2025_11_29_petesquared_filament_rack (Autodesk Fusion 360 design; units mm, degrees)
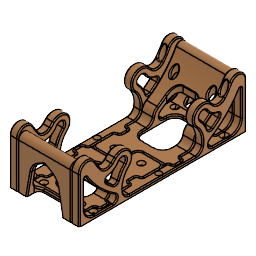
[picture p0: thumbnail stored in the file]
parameter "global_cutout_corner_round" = 25.4
parameter "hole_screw" = 3.2004
parameter "hole_screwhead" = 7.112
parameter "d545" = 25.4
parameter "d546" = 25.4 (= "d545")
sketch "filament_rack_side" plane through (0, 0, 0) normal (1, 0, 0) x axis (0, 1, 0)
  line L1 (-10.5228, -408.051) -> (33.0228, -408.051)
  line L2 (134.6228, -401.701) -> (134.6228, -300.101)
  line L3 (238.7628, -300.101) -> (238.7628, -408.051)
  line L4 (134.6228, -408.051) -> (134.6228, -404.241)
  line L5 (238.7628, -408.051) -> (134.6228, -408.051)
  line L6 (236.2228, -300.101) -> (134.6228, -300.101)
  line L7 (232.4128, -391.541) -> (232.4128, -358.92)
  line L8 (219.7128, -404.241) -> (196.5801, -404.241)
  line L9 (175.7042, -404.241) -> (134.6228, -404.241)
  line L10 (121.9228, -404.241) -> (134.6228, -404.241)
  line L11 (121.9228, -408.051) -> (121.9228, -404.241)
  line L12 (134.6228, -408.051) -> (121.9228, -408.051)
  line L13 (198.0923, -359.4264) -> (194.1136, -355.4477)
  circle C1 centre (134.6228, -300.101) radius 101.6
  circle C2 centre (134.6228, -300.101) radius 104.14
  arc A1 centre (232.4128, -351.5321) radius 6.35 clockwise from (226.7927, -348.5763) to (238.7628, -351.5321)
  arc A2 centre (134.6228, -300.101) radius 111.76 clockwise from (230.0583, -358.2591) to (193.8863, -394.854)
  arc A3 centre (219.7128, -391.541) radius 12.7 clockwise from (232.4128, -391.541) to (219.7128, -404.241)
  arc A4 centre (196.5801, -399.161) radius 5.08 clockwise from (196.5801, -404.241) to (193.8863, -394.854)
  arc A5 centre (231.1428, -358.92) radius 1.27 clockwise from (230.0583, -358.2591) to (232.4128, -358.92)
  arc A6 centre (175.7042, -395.7956) radius 8.4454 clockwise from (184.0419, -397.1397) to (175.7042, -404.241)
  arc A7 centre (196.5801, -399.161) radius 12.7 clockwise from (184.0419, -397.1397) to (189.8456, -388.3936)
  arc A8 centre (134.6228, -300.101) radius 96.52 clockwise from (219.2429, -346.5289) to (197.3331, -373.4736)
  arc A9 centre (228.3617, -351.5321) radius 10.4011 clockwise from (219.2429, -346.5289) to (238.7628, -351.5321)
  arc A10 centre (222.9164, -403.4067) radius 39.3763 clockwise from (184.0419, -397.1397) to (197.3331, -373.4736)
  arc A11 centre (157.3505, -392.8368) radius 27.036 clockwise from (176.2537, -373.5077) to (184.0419, -397.1397)
  arc A12 centre (185.1334, -364.428) radius 12.7 clockwise from (176.2537, -373.5077) to (194.1136, -355.4477)
  arc A13 centre (204.3785, -353.1402) radius 8.89 clockwise from (211.4552, -358.521) to (198.0923, -359.4264)
  arc A14 centre (157.3505, -392.8368) radius 34.656 clockwise from (181.5815, -368.0599) to (191.5609, -387.2973)
  arc A15 centre (204.3785, -353.8284) radius 16.891 clockwise from (213.6024, -367.9785) to (189.5831, -361.9772)
  arc A16 centre (185.1334, -364.428) radius 5.08 clockwise from (181.5815, -368.0599) to (189.5831, -361.9772)
  point P2 (134.6228, -300.101)
  point P5 (134.6228, -300.101)
  point P6 (134.6228, -401.701)
  point P10 (238.7628, -300.101)
  point P3 (33.0228, -408.051)
  point P11 (238.7628, -408.051)
  point P8 (134.6228, -404.241)
  point P14 (226.7927, -348.5763)
  point P13 (238.7628, -351.5321)
  point P16 (134.6228, -300.101)
  point P17 (236.2228, -300.101)
  point P9 (238.7628, -408.051)
  point P31 (189.8456, -388.3936)
  point P26 (196.5801, -399.161)
  point P32 (196.5801, -399.161)
  point P30 (175.7042, -395.7956)
  point P23 (196.5801, -404.241)
  point P28 (175.7042, -404.241)
  point P35 (134.6228, -300.101)
  point P45 (211.4552, -358.521)
  point P40 (176.2537, -373.5077)
  point P42 (176.2537, -373.5077)
  point P50 (191.5609, -387.2973)
  point P53 (189.5831, -361.9772)
  point P54 (213.6024, -367.9785)
  point P55 (189.5831, -361.9772)
  point P47 (204.3785, -353.1402)
  point P52 (204.3785, -353.8284)
  point P33 (121.9228, -404.241)
  point P44 (185.1334, -364.428)
  coincident P2 P5
  vertical L2
  coincident C1 P6
  coincident C2 P10
  vertical L3
  horizontal P3 P11
  vertical P6 P8
  horizontal L5
  tangent C2 A1
  coincident C2 P14
  coincident L3 P13
  tangent L3 A1
  coincident P2 P16
  coincident C1 P17
  perpendicular L2 L6
  horizontal P10 P17
  vertical L7
  horizontal L8
  tangent L8 A3
  tangent L7 A3
  tangent L8 A4
  tangent L7 A5
  tangent A2 A5
  coincident P9 P11
  vertical L4
  coincident C2 P8
  tangent C2 L9
  tangent L9 A6
  tangent C2 A7
  coincident C2 P31
  tangent A6 A7
  coincident P26 P32
  tangent C2 L10
  perpendicular L5 L11
  perpendicular L4 L12
  coincident C2 P30
  horizontal P23 P28
  coincident P5 P35
  tangent L3 A9
  tangent A8 A9
  tangent A8 A10
  tangent A6 A10
  tangent A10 A11
  coincident A8 P45
  tangent A8 A13
  tangent A12 L13
  tangent A13 L13
  coincident P40 P42
  tangent A11 A12
  concentric A12 A16
  tangent A14 A16
  concentric A11 A14
  coincident C2 P50
  coincident P53 A16
  coincident C2 P54
  coincident A15 P55
  tangent A2 A4
  tangent A15 A16
  vertical P47 P52
  dimension "d2084" diameter C1 = 203.2
  dimension "d2088" distance P3 L2 = 101.6
  dimension "d2089" distance P3 P6 = 6.35
  dimension "d2090" = 2.54
  dimension "d2092" radius A1 = 6.35 (= "global_cutout_corner_round / 4")
  dimension "d2093" radius A3 = 12.7
  dimension "d2094" distance L3 L7 = 6.35
  dimension "d2096" radius A4 = 5.08
  dimension "d2097" radius A5 = 1.27
  dimension "d2100" distance C1 A2 = 10.16
  dimension "d2101" distance P8 P33 = 12.7
  dimension "d2200" distance C1 A8 = 5.08
  dimension "d2205" radius A12 = 12.7
  dimension "d2207" radius A13 = 8.89
  dimension "d2208" angle L5 L13 = 45
  dimension "d2209" distance P9 P45 = 49.53
  dimension "d2210" diameter A16 = 10.16
  dimension "d2212" distance C2 P44 = 22.352
  dimension "d2213" radius A15 = 16.891
extrude "Extrude1" new body sketch "filament_rack_side" profile of C2 L3 L4 L5 A1 A2 L7 L8 A3 A4 A5 L9 A6 A7 L10 L11 L12 along normal blind 66.675 (= "2 5/8")
sketch "filament_rack_bottom" plane through (0, 0, -408.051) normal (0, 0, 1) x axis (1, 0, 0)
  line L1 (0, 134.6228) -> (0, 121.9228)
  line L2 (0, 238.7628) -> (0, 134.6228)
  line L3 (0, 134.6228) -> (66.675, 134.6228)
  line L4 (66.675, 238.7628) -> (0, 238.7628)
  line L5 (66.675, 134.6228) -> (66.675, 238.7628)
  line L6 (40.9575, 210.8228) -> (25.7175, 210.8228)
  line L7 (51.1175, 170.1828) -> (51.1175, 200.6628)
  line L8 (25.7175, 160.0228) -> (40.9575, 160.0228)
  line L9 (15.5575, 200.6628) -> (15.5575, 170.1828)
  line L10 (66.675, 134.6228) -> (66.675, 121.9228)
  line L11 (66.675, 219.7128) -> (0, 219.7128)
  line L12 (66.675, 147.3228) -> (0, 147.3228)
  line L13 (73.025, 200.0278) -> (73.025, 206.3778)
  line L14 (60.325, 200.0278) -> (60.325, 206.3778)
  line L15 (66.675, 121.9228) -> (0, 121.9228)
  line L16 (33.3375, 238.7628) -> (33.3375, 121.9228)
  line L17 (72.8726, 200.0278) -> (72.8726, 206.3778)
  line L18 (60.4774, 200.0278) -> (60.4774, 206.3778)
  line L19 (-6.1976, 200.0278) -> (-6.1976, 206.3778)
  line L20 (6.1976, 200.0278) -> (6.1976, 206.3778)
  line L21 (6.35, 200.0278) -> (6.35, 206.3778)
  line L22 (-6.35, 200.0278) -> (-6.35, 206.3778)
  line L23 (66.675, 180.3428) -> (0, 180.3428)
  line L24 (0, 238.7628) -> (0, 30.4828)
  line L25 (60.325, 160.6578) -> (60.325, 154.3078)
  line L26 (72.8726, 160.6578) -> (72.8726, 154.3078)
  line L27 (60.4774, 160.6578) -> (60.4774, 154.3078)
  line L28 (73.025, 160.6578) -> (73.025, 154.3078)
  line L29 (-6.1976, 160.6578) -> (-6.1976, 154.3078)
  line L30 (6.1976, 160.6578) -> (6.1976, 154.3078)
  line L31 (6.35, 160.6578) -> (6.35, 154.3078)
  line L32 (-6.35, 160.6578) -> (-6.35, 154.3078)
  line L33 (26.9875, 128.2728) -> (6.35, 128.2728)
  arc A1 centre (6.35, 128.2728) radius 6.35 clockwise from (6.35, 121.9228) to (0, 128.2728)
  arc A2 centre (26.9875, 128.2728) radius 6.35 clockwise from (33.3375, 128.2728) to (26.9875, 121.9228)
  circle C1 centre (16.6688, 134.6228) radius 1.6002
  arc A3 centre (25.7175, 200.6628) radius 10.16 clockwise from (15.5575, 200.6628) to (25.7175, 210.8228)
  arc A4 centre (40.9575, 200.6628) radius 10.16 clockwise from (40.9575, 210.8228) to (51.1175, 200.6628)
  arc A5 centre (40.9575, 170.1828) radius 10.16 clockwise from (51.1175, 170.1828) to (40.9575, 160.0228)
  arc A6 centre (25.7175, 170.1828) radius 10.16 clockwise from (25.7175, 160.0228) to (15.5575, 170.1828)
  circle C2 centre (10.16, 216.1568) radius 1.6002
  circle C3 centre (10.16, 216.1568) radius 3.556
  circle C4 centre (56.515, 216.1568) radius 1.6002
  circle C5 centre (56.515, 216.1568) radius 3.556
  arc A7 centre (39.6875, 140.9728) radius 6.35 clockwise from (33.3375, 140.9728) to (39.6875, 147.3228)
  arc A8 centre (69.85, 212.7278) radius 3.175 clockwise from (69.85, 209.5528) to (66.675, 212.7278)
  arc A9 centre (69.85, 206.3778) radius 3.175 clockwise from (69.85, 209.5528) to (73.025, 206.3778)
  arc A10 centre (69.85, 200.0278) radius 3.175 clockwise from (73.025, 200.0278) to (69.85, 196.8528)
  arc A11 centre (69.85, 193.6778) radius 3.175 clockwise from (66.675, 193.6778) to (69.85, 196.8528)
  arc A12 centre (63.5, 193.6778) radius 3.175 clockwise from (63.5, 196.8528) to (66.675, 193.6778)
  arc A13 centre (63.5, 200.0278) radius 3.175 clockwise from (63.5, 196.8528) to (60.325, 200.0278)
  arc A14 centre (63.5, 212.7278) radius 3.175 clockwise from (66.675, 212.7278) to (63.5, 209.5528)
  arc A15 centre (63.5, 206.3778) radius 3.175 clockwise from (60.325, 206.3778) to (63.5, 209.5528)
  arc A16 centre (69.85, 212.7278) radius 3.3274 clockwise from (69.85, 209.4004) to (66.675, 211.7323)
  arc A17 centre (69.85, 206.3778) radius 3.0226 clockwise from (69.85, 209.4004) to (72.8726, 206.3778)
  arc A18 centre (69.85, 200.0278) radius 3.0226 clockwise from (72.8726, 200.0278) to (69.85, 197.0052)
  arc A19 centre (69.85, 193.6778) radius 3.3274 clockwise from (66.675, 194.6733) to (69.85, 197.0052)
  arc A20 centre (63.5, 193.6778) radius 3.3274 clockwise from (63.5, 197.0052) to (66.675, 194.6733)
  arc A21 centre (63.5, 200.0278) radius 3.0226 clockwise from (63.5, 197.0052) to (60.4774, 200.0278)
  arc A22 centre (63.5, 206.3778) radius 3.0226 clockwise from (60.4774, 206.3778) to (63.5, 209.4004)
  arc A23 centre (63.5, 212.7278) radius 3.3274 clockwise from (66.675, 211.7323) to (63.5, 209.4004)
  arc A24 centre (-3.175, 206.3778) radius 3.0226 clockwise from (-6.1976, 206.3778) to (-3.175, 209.4004)
  arc A25 centre (-3.175, 200.0278) radius 3.0226 clockwise from (-3.175, 197.0052) to (-6.1976, 200.0278)
  arc A26 centre (-3.175, 193.6778) radius 3.3274 clockwise from (-3.175, 197.0052) to (0, 194.6733)
  arc A27 centre (3.175, 193.6778) radius 3.3274 clockwise from (0, 194.6733) to (3.175, 197.0052)
  arc A28 centre (3.175, 200.0278) radius 3.0226 clockwise from (6.1976, 200.0278) to (3.175, 197.0052)
  arc A29 centre (3.175, 206.3778) radius 3.0226 clockwise from (3.175, 209.4004) to (6.1976, 206.3778)
  arc A30 centre (-3.175, 212.7278) radius 3.3274 clockwise from (0, 211.7323) to (-3.175, 209.4004)
  arc A31 centre (3.175, 212.7278) radius 3.3274 clockwise from (3.175, 209.4004) to (0, 211.7323)
  arc A32 centre (3.175, 193.6778) radius 3.175 clockwise from (0, 193.6778) to (3.175, 196.8528)
  arc A33 centre (3.175, 200.0278) radius 3.175 clockwise from (6.35, 200.0278) to (3.175, 196.8528)
  arc A34 centre (3.175, 206.3778) radius 3.175 clockwise from (3.175, 209.5528) to (6.35, 206.3778)
  arc A35 centre (3.175, 212.7278) radius 3.175 clockwise from (3.175, 209.5528) to (0, 212.7278)
  arc A36 centre (-3.175, 206.3778) radius 3.175 clockwise from (-6.35, 206.3778) to (-3.175, 209.5528)
  arc A37 centre (-3.175, 200.0278) radius 3.175 clockwise from (-3.175, 196.8528) to (-6.35, 200.0278)
  arc A38 centre (-3.175, 193.6778) radius 3.175 clockwise from (-3.175, 196.8528) to (0, 193.6778)
  arc A39 centre (-3.175, 212.7278) radius 3.175 clockwise from (0, 212.7278) to (-3.175, 209.5528)
  arc A40 centre (63.5, 147.9578) radius 3.175 clockwise from (63.5, 151.1328) to (66.675, 147.9578)
  arc A41 centre (63.5, 154.3078) radius 3.175 clockwise from (63.5, 151.1328) to (60.325, 154.3078)
  arc A42 centre (63.5, 160.6578) radius 3.175 clockwise from (60.325, 160.6578) to (63.5, 163.8328)
  arc A43 centre (63.5, 167.0078) radius 3.175 clockwise from (66.675, 167.0078) to (63.5, 163.8328)
  arc A44 centre (63.5, 167.0078) radius 3.3274 clockwise from (66.675, 166.0123) to (63.5, 163.6804)
  arc A45 centre (69.85, 167.0078) radius 3.3274 clockwise from (69.85, 163.6804) to (66.675, 166.0123)
  arc A46 centre (69.85, 160.6578) radius 3.0226 clockwise from (69.85, 163.6804) to (72.8726, 160.6578)
  arc A47 centre (69.85, 154.3078) radius 3.0226 clockwise from (72.8726, 154.3078) to (69.85, 151.2852)
  arc A48 centre (69.85, 147.9578) radius 3.3274 clockwise from (66.675, 148.9533) to (69.85, 151.2852)
  arc A49 centre (63.5, 147.9578) radius 3.3274 clockwise from (63.5, 151.2852) to (66.675, 148.9533)
  arc A50 centre (63.5, 154.3078) radius 3.0226 clockwise from (63.5, 151.2852) to (60.4774, 154.3078)
  arc A51 centre (63.5, 160.6578) radius 3.0226 clockwise from (60.4774, 160.6578) to (63.5, 163.6804)
  arc A52 centre (69.85, 147.9578) radius 3.175 clockwise from (66.675, 147.9578) to (69.85, 151.1328)
  arc A53 centre (69.85, 154.3078) radius 3.175 clockwise from (73.025, 154.3078) to (69.85, 151.1328)
  arc A54 centre (69.85, 160.6578) radius 3.175 clockwise from (69.85, 163.8328) to (73.025, 160.6578)
  arc A55 centre (69.85, 167.0078) radius 3.175 clockwise from (69.85, 163.8328) to (66.675, 167.0078)
  arc A56 centre (3.175, 160.6578) radius 3.0226 clockwise from (3.175, 163.6804) to (6.1976, 160.6578)
  arc A57 centre (3.175, 167.0078) radius 3.3274 clockwise from (3.175, 163.6804) to (0, 166.0123)
  arc A58 centre (-3.175, 167.0078) radius 3.3274 clockwise from (0, 166.0123) to (-3.175, 163.6804)
  arc A59 centre (-3.175, 160.6578) radius 3.0226 clockwise from (-6.1976, 160.6578) to (-3.175, 163.6804)
  arc A60 centre (-3.175, 154.3078) radius 3.0226 clockwise from (-3.175, 151.2852) to (-6.1976, 154.3078)
  arc A61 centre (-3.175, 147.9578) radius 3.3274 clockwise from (-3.175, 151.2852) to (0, 148.9533)
  arc A62 centre (3.175, 147.9578) radius 3.3274 clockwise from (0, 148.9533) to (3.175, 151.2852)
  arc A63 centre (3.175, 154.3078) radius 3.0226 clockwise from (6.1976, 154.3078) to (3.175, 151.2852)
  arc A64 centre (3.175, 147.9578) radius 3.175 clockwise from (0, 147.9578) to (3.175, 151.1328)
  arc A65 centre (3.175, 154.3078) radius 3.175 clockwise from (6.35, 154.3078) to (3.175, 151.1328)
  arc A66 centre (3.175, 160.6578) radius 3.175 clockwise from (3.175, 163.8328) to (6.35, 160.6578)
  arc A67 centre (3.175, 167.0078) radius 3.175 clockwise from (3.175, 163.8328) to (0, 167.0078)
  arc A68 centre (-3.175, 147.9578) radius 3.175 clockwise from (-3.175, 151.1328) to (0, 147.9578)
  arc A69 centre (-3.175, 154.3078) radius 3.175 clockwise from (-3.175, 151.1328) to (-6.35, 154.3078)
  arc A70 centre (-3.175, 160.6578) radius 3.175 clockwise from (-6.35, 160.6578) to (-3.175, 163.8328)
  arc A71 centre (-3.175, 167.0078) radius 3.175 clockwise from (0, 167.0078) to (-3.175, 163.8328)
  circle C6 centre (-5.08, 134.6228) radius 1.6002
  circle C7 centre (-5.08, 216.1568) radius 1.6002
  circle C8 centre (-5.08, 216.1568) radius 3.556
  point P3 (0, 134.6228)
  point P6 (0, 134.6228)
  point P4 (0, 238.7628)
  point P7 (0, 238.7628)
  point P9 (0, 128.2728)
  point P28 (33.3375, 160.0228)
  point P36 (0, 147.3228)
  point P37 (66.675, 147.3228)
  point P39 (39.6875, 147.3228)
  point P41 (66.675, 212.7278)
  point P49 (66.675, 193.6778)
  point P43 (69.85, 212.7278)
  point P45 (69.85, 206.3778)
  point P59 (66.675, 212.7278)
  point P42 (69.85, 209.5528)
  point P60 (63.5, 209.5528)
  point P44 (73.025, 206.3778)
  point P57 (60.325, 206.3778)
  point P46 (73.025, 200.0278)
  point P56 (60.325, 200.0278)
  point P47 (69.85, 196.8528)
  point P53 (63.5, 196.8528)
  point P54 (66.675, 193.6778)
  point P2 (0, 121.9228)
  point P62 (0, 121.9228)
  point P63 (33.3375, 121.9228)
  point P64 (33.3375, 238.7628)
  point P38 (33.3375, 140.9728)
  point P13 (33.3375, 128.2728)
  point P12 (26.9875, 121.9228)
  point P31 (10.16, 216.1568)
  point P35 (56.515, 216.1568)
  point P34 (56.515, 216.1568)
  point P65 (33.3375, 180.3428)
  point P121 (0, 212.7278)
  point P114 (-3.175, 209.5528)
  point P113 (-6.35, 206.3778)
  point P115 (-6.35, 200.0278)
  point P117 (-3.175, 196.8528)
  point P119 (0, 193.6778)
  point P104 (3.175, 196.8528)
  point P103 (0, 193.6778)
  point P106 (6.35, 200.0278)
  point P107 (6.35, 206.3778)
  point P111 (0, 212.7278)
  point P109 (3.175, 209.5528)
  point P67 (69.85, 209.4004)
  point P86 (-3.175, 209.4004)
  point P68 (66.675, 211.7323)
  point P100 (0, 211.7323)
  point P70 (72.8726, 206.3778)
  point P85 (-6.1976, 206.3778)
  point P71 (72.8726, 200.0278)
  point P87 (-6.1976, 200.0278)
  point P73 (69.85, 197.0052)
  point P89 (-3.175, 197.0052)
  point P75 (66.675, 194.6733)
  point P91 (0, 194.6733)
  point P77 (63.5, 197.0052)
  point P93 (3.175, 197.0052)
  point P79 (60.4774, 200.0278)
  point P95 (6.1976, 200.0278)
  point P80 (60.4774, 206.3778)
  point P96 (6.1976, 206.3778)
  point P82 (63.5, 209.4004)
  point P98 (3.175, 209.4004)
  point P122 (0, 180.3428)
  point P155 (66.675, 147.9578)
  point P156 (69.85, 151.1328)
  point P158 (73.025, 154.3078)
  point P159 (73.025, 160.6578)
  point P161 (69.85, 163.8328)
  point P163 (66.675, 167.0078)
  point P133 (63.5, 163.8328)
  point P135 (66.675, 167.0078)
  point P131 (60.325, 160.6578)
  point P130 (60.325, 154.3078)
  point P128 (66.675, 147.9578)
  point P127 (63.5, 151.1328)
  point P145 (69.85, 151.2852)
  point P147 (66.675, 148.9533)
  point P143 (72.8726, 154.3078)
  point P142 (72.8726, 160.6578)
  point P140 (69.85, 163.6804)
  point P137 (66.675, 166.0123)
  point P138 (63.5, 163.6804)
  point P152 (60.4774, 160.6578)
  point P151 (60.4774, 154.3078)
  point P149 (63.5, 151.2852)
  point P173 (-6.1976, 154.3078)
  point P175 (-3.175, 151.2852)
  point P172 (-6.1976, 160.6578)
  point P170 (-3.175, 163.6804)
  point P168 (0, 166.0123)
  point P165 (3.175, 163.6804)
  point P166 (6.1976, 160.6578)
  point P181 (6.1976, 154.3078)
  point P179 (3.175, 151.2852)
  point P177 (0, 148.9533)
  point P191 (0, 167.0078)
  point P188 (3.175, 163.8328)
  point P189 (6.35, 160.6578)
  point P186 (6.35, 154.3078)
  point P184 (3.175, 151.1328)
  point P183 (0, 147.9578)
  point P196 (-6.35, 154.3078)
  point P193 (-3.175, 151.1328)
  point P198 (-6.35, 160.6578)
  point P199 (-3.175, 163.8328)
  point P201 (0, 167.0078)
  point P194 (0, 147.9578)
  point P10 (6.35, 121.9228)
  point P11 (6.35, 128.2728)
  point P202 (6.35, 128.2728)
  point P14 (26.9875, 128.2728)
  point P203 (26.9875, 128.2728)
  point P15 (16.6688, 134.6228)
  point P204 (16.6688, 128.2728)
  point P205 (-5.08, 134.6228)
  point P206 (0, 134.6228)
  point P207 (-5.08, 216.1568)
  point P5 (66.675, 134.6228)
  point P32 (0, 219.7128)
  coincident P3 P6
  horizontal L3
  coincident P4 P7
  perpendicular L3 L5
  coincident L1 P9
  tangent L1 A1
  equal A1 A2
  horizontal L4
  horizontal L6
  vertical L7
  horizontal L8
  vertical L9
  tangent L9 A3
  tangent L6 A3
  tangent L6 A4
  tangent L7 A4
  equal A3 A4
  tangent L7 A5
  tangent L8 A5
  equal A3 A5
  tangent L8 A6
  tangent L9 A6
  equal A3 A6
  midpoint L8 P28
  vertical L10
  concentric C2 C3
  tangent C3 L11
  coincident L2 P36
  coincident L5 P37
  perpendicular L5 L12
  tangent L12 A7
  coincident L12 P39
  equal A2 A7
  coincident L5 P41
  tangent L5 A8
  tangent L13 A9
  tangent L13 A10
  equal A9 A10
  tangent L5 A11
  coincident L5 P49
  equal A8 A11
  tangent A8 A9
  tangent A10 A11
  equal A8 A9
  vertical P43 P45
  symmetric L5 P41 P59
  symmetric L5 P42 P60
  symmetric L5 A8 A14
  symmetric L5 P44 P57
  symmetric L5 A9 A15
  symmetric L5 P46 P56
  symmetric L5 P47 P53
  symmetric L5 A10 A13
  symmetric L5 P49 P54
  symmetric L5 A11 A12
  coincident P2 P62
  perpendicular L1 L15
  midpoint L15 P63
  midpoint L4 P64
  coincident P38 L16
  coincident P13 L16
  tangent A7 L16
  tangent A2 L16
  coincident P12 L15
  tangent A2 L15
  coincident P28 L16
  horizontal P31 P35
  coincident P34 P35
  coincident L16 P65
  midpoint L16 P65
  symmetric P41 L16 P121
  symmetric P42 L16 P114
  symmetric A8 L16 A39
  symmetric P44 L16 P113
  symmetric A9 L16 A36
  symmetric P46 L16 P115
  symmetric P47 L16 P117
  symmetric A10 L16 A37
  symmetric P49 L16 P119
  symmetric A11 L16 A38
  symmetric P53 L16 P104
  symmetric P54 L16 P103
  symmetric A12 L16 A32
  symmetric P56 L16 P106
  symmetric A13 L16 A33
  symmetric P57 L16 P107
  symmetric P59 L16 P111
  symmetric P60 L16 P109
  symmetric A14 L16 A35
  symmetric A15 L16 A34
  symmetric L16 P67 P86
  symmetric L16 P68 P100
  symmetric L16 A16 A30
  symmetric L16 P70 P85
  symmetric L16 A17 A24
  symmetric L16 P71 P87
  symmetric L16 P73 P89
  symmetric L16 A18 A25
  symmetric L16 P75 P91
  symmetric L16 A19 A26
  symmetric L16 P77 P93
  symmetric L16 A20 A27
  symmetric L16 P79 P95
  symmetric L16 A21 A28
  symmetric L16 P80 P96
  symmetric L16 P82 P98
  symmetric L16 A22 A29
  symmetric L16 A23 A31
  perpendicular L2 L23
  midpoint P65 L23
  coincident P122 L24
  symmetric P41 L23 P155
  symmetric P42 L23 P156
  symmetric A8 L23 A52
  symmetric P44 L23 P158
  symmetric A9 L23 A53
  symmetric P46 L23 P159
  symmetric P47 L23 P161
  symmetric A10 L23 A54
  symmetric P49 L23 P163
  symmetric A11 L23 A55
  symmetric P53 L23 P133
  symmetric P54 L23 P135
  symmetric A12 L23 A43
  symmetric P56 L23 P131
  symmetric A13 L23 A42
  symmetric P57 L23 P130
  symmetric P59 L23 P128
  symmetric P60 L23 P127
  symmetric A14 L23 A40
  symmetric A15 L23 A41
  symmetric P67 L23 P145
  symmetric P68 L23 P147
  symmetric A16 L23 A48
  symmetric P70 L23 P143
  symmetric A17 L23 A47
  symmetric P71 L23 P142
  symmetric P73 L23 P140
  symmetric A18 L23 A46
  symmetric P75 L23 P137
  symmetric A19 L23 A45
  symmetric P77 L23 P138
  symmetric A20 L23 A44
  symmetric P79 L23 P152
  symmetric A21 L23 A51
  symmetric P80 L23 P151
  symmetric P82 L23 P149
  symmetric A22 L23 A50
  symmetric A23 L23 A49
  symmetric P85 L23 P173
  symmetric P86 L23 P175
  symmetric A24 L23 A60
  symmetric P87 L23 P172
  symmetric P89 L23 P170
  symmetric A25 L23 A59
  symmetric P91 L23 P168
  symmetric A26 L23 A58
  symmetric P93 L23 P165
  symmetric A27 L23 A57
  symmetric P95 L23 P166
  symmetric A28 L23 A56
  symmetric P96 L23 P181
  symmetric P98 L23 P179
  symmetric A29 L23 A63
  symmetric P100 L23 P177
  symmetric A30 L23 A61
  symmetric A31 L23 A62
  symmetric P103 L23 P191
  symmetric P104 L23 P188
  symmetric A32 L23 A67
  symmetric P106 L23 P189
  symmetric A33 L23 A66
  symmetric P107 L23 P186
  symmetric P109 L23 P184
  symmetric A34 L23 A65
  symmetric P111 L23 P183
  symmetric A35 L23 A64
  symmetric P113 L23 P196
  symmetric P114 L23 P193
  symmetric A36 L23 A69
  symmetric P115 L23 P198
  symmetric P117 L23 P199
  symmetric A37 L23 A70
  symmetric P119 L23 P201
  symmetric A38 L23 A71
  symmetric P121 L23 P194
  symmetric A39 L23 A68
  coincident P10 L15
  tangent A1 L15
  coincident P11 P202
  coincident P14 P203
  coincident L3 P15
  midpoint L33 P204
  vertical P15 P204
  horizontal P205 P206
  horizontal P31 P207
  vertical P205 P207
  concentric C7 C8
  dimension "d2105" radius A1 = 6.35
  dimension "d2107" diameter C1 = 3.2004 (= "hole_screw")
  dimension "d2108" distance P2 P5 = 66.675 (= "2 5/8")
  dimension "d2110" radius A3 = 10.16
  dimension "d2111" distance L6 L8 = 50.8
  dimension "d2112" distance L7 L9 = 35.56
  dimension "d2114" diameter C2 = 3.2004 (= "hole_screw")
  dimension "d2115" diameter C3 = 7.112 (= "hole_screwhead")
  dimension "d2116" distance P31 P32 = 10.16
  dimension "d2140" distance L5 L13 = 6.35
  dimension "d2141" distance P44 P46 = 6.35
  dimension "d2143" distance P6 P36 = 12.7
  dimension "d2144" distance L5 P34 = 10.16 (= "d2116")
  dimension "d2145" diameter C4 = 3.2004 (= "hole_screw")
  dimension "d2146" diameter C5 = 7.112 (= "hole_screwhead")
  dimension "d2147" distance P54 P65 = 13.335
  dimension "d2148" = 0.1524
  dimension "d2159" distance L8 L12 = 12.7
  dimension "d2185" diameter C6 = 3.2004 (= "hole_screw")
  dimension "d2186" distance P205 P206 = 5.08
  dimension "d2187" diameter C7 = 3.2004 (= "hole_screw")
  dimension "d2188" diameter C8 = 7.112 (= "hole_screwhead")
extrude "Extrude2" cut sketch "filament_rack_bottom" profile of L1 L5 A1 A2 C1 L6 L7 L8 L9 A3 A4 A5 A6 L10 C2 C4 L12 A7 L15 L16 L24 no distance stored
extrude "Extrude3" sketch "filament_rack_bottom" profile of C2 C3 C4 C5 no distance stored
extrude "Extrude4" add sketch "filament_rack_bottom" profile of L2 L5 A24 L19 A25 A26 A30 L24 A45 A46 L26 A47 A48 to an object
extrude "Extrude5" cut sketch "filament_rack_bottom" profile of L2 L5 A12 A13 L14 A14 A15 A21 A20 L18 A22 A23 L24 A56 A57 A62 A63 L30 A64 A65 A66 A67 L31 to an object offset 2.54
sketch "filament_rack_back" plane through (0, 238.7628, 0) normal (0, 1, 0) x axis (-1, 0, 0)
  line L1 (0, -351.5321) -> (0, -408.051)
  line L2 (-66.675, -351.5321) -> (0, -351.5321)
  line L3 (-66.675, -408.051) -> (-66.675, -351.5321)
  line L4 (0, -408.051) -> (-66.675, -408.051)
  line L5 (-66.675, -408.051) -> (0, -408.051)
  line L6 (-66.675, -351.5321) -> (0, -351.5321)
  line L7 (-33.3375, -408.051) -> (-33.3375, -351.5321)
  line L8 (-66.675, -358.92) -> (0, -358.92)
  line L9 (-25.2735, -366.1157) -> (-33.3375, -361.46)
  line L10 (-11.43, -408.051) -> (-16.6537, -378.4262)
  line L11 (-41.4015, -366.1157) -> (-33.3375, -361.46)
  line L12 (-55.245, -408.051) -> (-50.0213, -378.4262)
  arc A1 centre (-34.1635, -381.5136) radius 17.78 clockwise from (-25.2735, -366.1157) to (-16.6537, -378.4262)
  arc A2 centre (-32.5115, -381.5136) radius 17.78 clockwise from (-50.0213, -378.4262) to (-41.4015, -366.1157)
  point P10 (-33.3375, -351.5321)
  point P11 (-33.3375, -408.051)
  point P14 (-33.3375, -361.46)
  point P18 (-11.43, -408.051)
  point P20 (-33.3375, -361.46)
  point P15 (-25.2735, -366.1157)
  point P21 (-41.4015, -366.1157)
  point P16 (-16.6537, -378.4262)
  point P23 (-50.0213, -378.4262)
  point P24 (-55.245, -408.051)
  point P19 (0, -408.051)
  midpoint L6 P10
  midpoint L5 P11
  coincident L7 P14
  tangent L9 A1
  coincident L5 P18
  tangent A1 L10
  symmetric L7 P14 P20
  symmetric L7 P15 P21
  symmetric L7 P16 P23
  symmetric L7 A1 A2
  symmetric L7 P18 P24
  dimension "d2149" angle L7 L9 = 60
  dimension "d2150" distance L8 P14 = 2.54
  dimension "d2151" distance P18 P19 = 11.43
  dimension "d2152" angle L5 L10 = 80
  dimension "d2153" radius A1 = 17.78
extrude "Extrude6" new body sketch "filament_rack_back" profile of L4 L5 L9 A1 L10 L11 A2 L12 against normal blind 15.24
draft "Draft1" Angle1 -10 Angle2 0
combine "Combine1"
extrude "Extrude7" new body sketch "filament_rack_side" profile of C2 L3 L4 L5 A1 A2 L7 L8 A3 A4 A5 L9 A6 A7 A8 A9 A10 A11 A12 A13 L13 A16 A14 A15 against normal blind 10.16 bodies "filament_rack_side_left"
fillet "Fillet4" radius 3.81
extrude "Extrude8" cut sketch "filament_rack_bottom" profile of C6 C7 to an object
extrude "Extrude9" sketch "filament_rack_bottom" profile of C7 C8 no distance stored
work_plane "WorkPlane1" RotateAngle 90
mirror "Mirror1" mirrorStitchTolerance 0.1016
extrude "Extrude10" cut sketch "filament_rack_bottom" profile of L2 L5 A24 L19 A25 A26 A30 A36 L22 A37 A38 A39 L24 A45 A46 L26 A47 A48 A52 A53 L28 A54 A55 along normal blind 5.08
extrude "Extrude11" add sketch "filament_rack_bottom" profile of L2 L5 A21 A20 L18 A22 A23 L24 A56 A57 A62 A63 L30 to an object
copy_paste_bodies "CopyPasteBodies2"
move "Move3"
move "Move4"
combine "Combine3" bodies "filament_rack_side_left (2)", "filament_rack_side_left", "filament_rack_side_left (1) (1)"
fillet "Fillet2" radius 6.096
fillet "Fillet1" radius 1.27
fillet "Fillet5" radius 1.016
sketch "center_axis" plane through (33.3375, 0, 0) normal (1, 0, 0) x axis (0, 1, 0)
  line L1 (134.6228, -395.351) -> (134.6228, -408.051)
  point P2 (134.6228, -408.051)
  point P5 (134.6228, -408.051)
  point P3 (134.6228, -395.351)
  vertical L1
  coincident P2 P5
  dimension "d2203" distance P2 P3 = 12.7
copy_paste_bodies "CopyPasteBodies3"
move "Move5" RotateAngle 180
chamfer "Chamfer3" distance 2.54 distance 3.048
draft "Draft2" Angle1 28 Angle2 0
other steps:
base_feature "Base Feature2" bodies "filament_rack_side_left", "filament_rack_side_left (1)", "filament_rack_side_left (2)", "filament_rack_side_left (1) (1)"
base_feature "Base Feature3" bodies "filament_rack_right", "filament_rack_left"
create_component "CreateComponent4"
create_component "CreateComponent2"
named bodies: "filament_rack_right", "filament_rack_side_left", "filament_rack_side_left (1)", "filament_rack_side_left (2)", "filament_rack_side_left (1) (1)", "filament_rack_side_right", "filament_rack_left"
